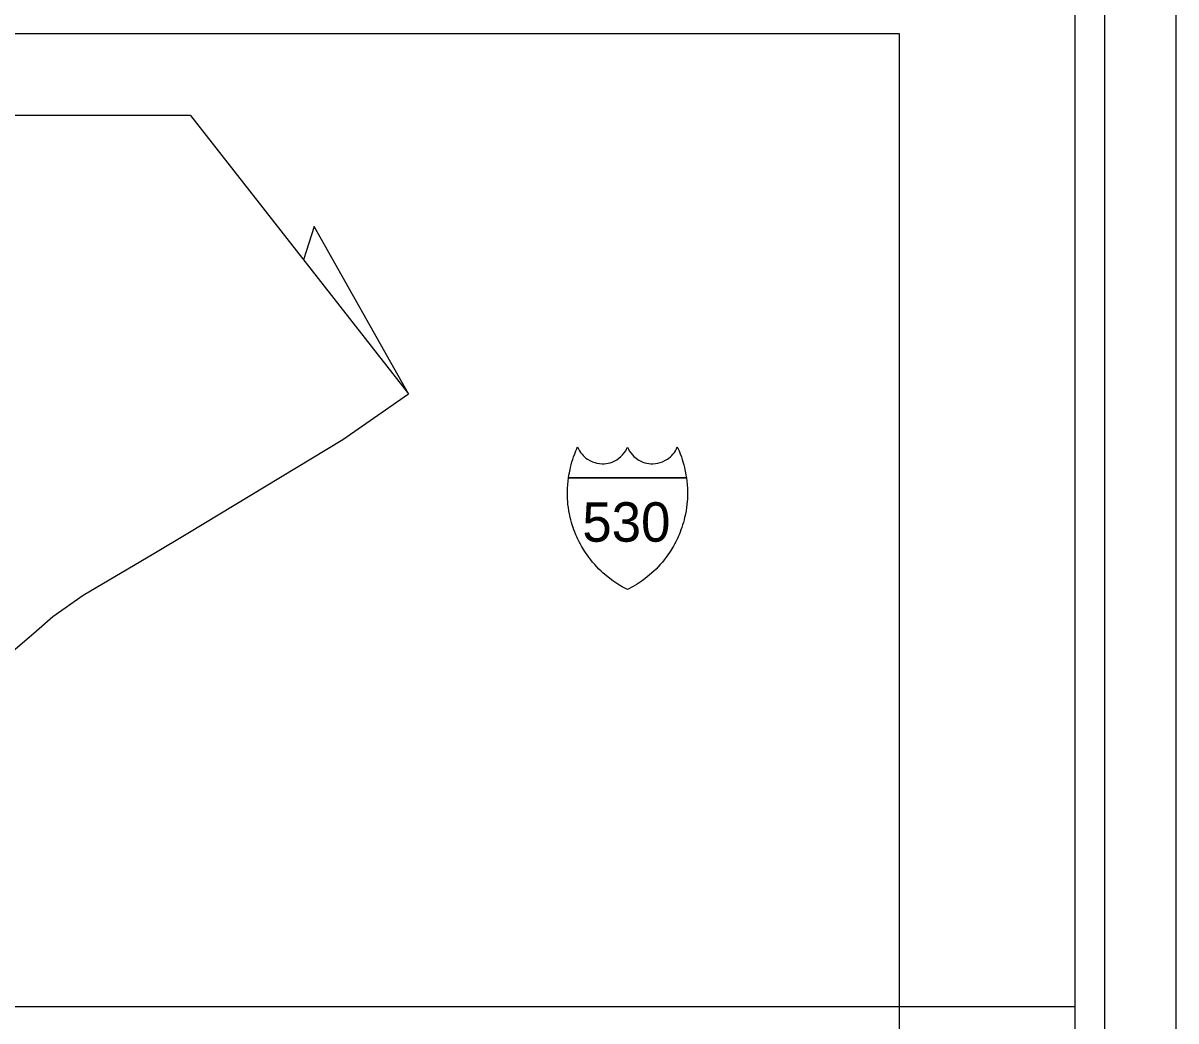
# Model space of a CAD drawing. Extents: x 10700 to 22009, y 10612 to 15552.
# Drawn here: x 16875 to 17646, y 14496 to 15164 of the extents above; entities that cross this region are included whole.
import ezdxf

# ---------------------------------------------------------------- set-up
doc = ezdxf.new("R2010")
doc.units = 0
for name, color, linetype in [('23', 7, 'Continuous'), ('Default', 7, 'Continuous'), ('R_Border', 7, 'Continuous'), ('R_Dimension', 7, 'Continuous'), ('R_No Plot', 7, 'Continuous')]:
    doc.layers.add(name, color=color, linetype=linetype)

msp = doc.modelspace()

# ---------------------------------------------------------------- linework, layer by layer
at = {"layer": '23'}
for points in [[(17239.63, 14859.64), (17239.92, 14861.53), (17240.22, 14863.19), (17240.66, 14865.34), (17240.98, 14866.74), (17241.4, 14868.41), (17241.95, 14870.36), (17242.46, 14871.99), (17243.02, 14873.68), (17243.77, 14875.75), (17244.55, 14877.69), (17245.19, 14879.19), (17245.73, 14880.38), (17246.31, 14879.1), (17246.98, 14877.88), (17247.71, 14876.76), (17248.67, 14875.52), (17249.43, 14874.68), (17250.37, 14873.77), (17251.32, 14872.98), (17252.35, 14872.23), (17253.98, 14871.25), (17255.66, 14870.47), (17257.18, 14869.93), (17258.68, 14869.54), (17260.29, 14869.28), (17262.16, 14869.15), (17263.39, 14869.18), (17264.81, 14869.31), (17266.06, 14869.52), (17267.41, 14869.86), (17268.77, 14870.31), (17270.59, 14871.11), (17271.85, 14871.81), (17273.31, 14872.81), (17274.71, 14873.99), (17275.74, 14875.03), (17276.9, 14876.44), (17277.87, 14877.89), (17278.43, 14878.9), (17279.06, 14880.23)], [(17279.06, 14880.23), (17279.68, 14878.9), (17280.24, 14877.89), (17281.21, 14876.44), (17282.38, 14875.03), (17283.4, 14873.99), (17284.8, 14872.81), (17286.26, 14871.81), (17287.52, 14871.11), (17289.35, 14870.31), (17290.7, 14869.86), (17292.05, 14869.52), (17293.31, 14869.31), (17294.72, 14869.18), (17295.95, 14869.15), (17297.82, 14869.28), (17299.43, 14869.54), (17300.93, 14869.93), (17302.45, 14870.47), (17304.13, 14871.25), (17305.76, 14872.23), (17306.79, 14872.98), (17307.74, 14873.77), (17308.68, 14874.68), (17309.44, 14875.52), (17310.4, 14876.76), (17311.13, 14877.88), (17311.8, 14879.1), (17312.39, 14880.38), (17312.92, 14879.19), (17313.57, 14877.69), (17314.34, 14875.75), (17315.09, 14873.68), (17315.65, 14871.99), (17316.16, 14870.36), (17316.71, 14868.41), (17317.13, 14866.74), (17317.45, 14865.34), (17317.9, 14863.19), (17318.19, 14861.53), (17318.48, 14859.64)], [(17279.06, 14784.95), (17275.6, 14786.8), (17272.56, 14788.62), (17269.22, 14790.88), (17266.1, 14793.25), (17262.68, 14796.16), (17261.41, 14797.34), (17259.96, 14798.76), (17258.62, 14800.14), (17257.15, 14801.75), (17255.71, 14803.43), (17254.51, 14804.91), (17253.2, 14806.61), (17252.02, 14808.25), (17250.99, 14809.76), (17250.09, 14811.15), (17249.34, 14812.35), (17248.36, 14814.04), (17247.59, 14815.42), (17246.74, 14817.03), (17245.92, 14818.69), (17245.21, 14820.24), (17244.56, 14821.72), (17243.88, 14823.39), (17243.29, 14824.94), (17242.72, 14826.56), (17242.17, 14828.25), (17241.65, 14829.97), (17241.2, 14831.62), (17240.81, 14833.19), (17240.49, 14834.59), (17240.28, 14835.62), (17239.9, 14837.63), (17239.54, 14839.95), (17239.29, 14841.88), (17239.12, 14843.91), (17239.01, 14845.56), (17238.93, 14847.65), (17238.91, 14849.6), (17238.95, 14851.77), (17239.01, 14853.2), (17239.09, 14854.51), (17239.15, 14855.33), (17239.36, 14857.46), (17239.63, 14859.64)], [(17318.48, 14859.64), (17239.63, 14859.64)], [(17239.63, 14859.64), (17318.48, 14859.64)], [(17318.48, 14859.64), (17318.75, 14857.46), (17318.96, 14855.33), (17319.02, 14854.51), (17319.1, 14853.2), (17319.16, 14851.77), (17319.2, 14849.6), (17319.18, 14847.65), (17319.1, 14845.56), (17319, 14843.91), (17318.82, 14841.88), (17318.57, 14839.95), (17318.21, 14837.63), (17317.84, 14835.62), (17317.62, 14834.59), (17317.3, 14833.19), (17316.91, 14831.62), (17316.46, 14829.97), (17315.94, 14828.25), (17315.39, 14826.56), (17314.82, 14824.94), (17314.23, 14823.39), (17313.55, 14821.72), (17312.9, 14820.24), (17312.19, 14818.69), (17311.37, 14817.03), (17310.52, 14815.42), (17309.76, 14814.04), (17308.77, 14812.35), (17308.03, 14811.15), (17307.12, 14809.76), (17306.1, 14808.25), (17304.91, 14806.61), (17303.61, 14804.91), (17302.4, 14803.43), (17300.96, 14801.75), (17299.49, 14800.14), (17298.15, 14798.76), (17296.7, 14797.34), (17295.43, 14796.16), (17292.02, 14793.25), (17288.89, 14790.88), (17285.55, 14788.62), (17282.51, 14786.8), (17279.06, 14784.95)]]:
    msp.add_lwpolyline(points, dxfattribs=at)
at = {"layer": 'Default'}
msp.add_lwpolyline([(16155.5, 14168.76), (16185.52, 14183.02), (16215.54, 14197.28), (16237.97, 14209.07), (16270.34, 14229.5), (16275.18, 14233.24), (16281.02, 14238.26), (16394.9, 14334.16), (16410.98, 14348.21), (16776.96, 14665.71), (16798.8, 14684.66), (16813.62, 14697.51), (16824.46, 14706.35), (16863.46, 14739.87), (16883.94, 14757.47), (16894.9, 14766.9), (16915.02, 14781.31), (16962.44, 14809.09), (16985.03, 14822.73), (17088.74, 14885.33), (17132.75, 14915.87)], dxfattribs=at)
at = {"layer": 'R_Border'}
msp.add_line((17598.27, 13458.53), (17598.27, 15513.13), dxfattribs=at)
at = {"layer": 'R_Dimension'}
msp.add_line((16986.85, 15102.14), (16565.62, 15102.14), dxfattribs=at)
msp.add_lwpolyline([(16986.85, 15102.14), (17132.75, 14915.87), (17069.65, 15027.91), (17062.51, 15005.55)], dxfattribs=at)
at = {"layer": 'R_No Plot'}
for points in [[(14312.4, 15552.08), (17645.8, 15552.08), (17645.8, 13418.7), (14312.4, 13418.7)], [(14456.47, 15493.13), (16951.87, 15493.13), (16951.87, 15394.33), (17127.27, 15394.33), (17368.27, 15394.33), (17368.27, 15171.01), (17578.27, 15171.01), (17578.27, 13478.53), (14456.47, 13478.53)], [(17578.27, 14505.83), (14456.47, 14505.83), (14456.47, 15493.13), (16951.87, 15493.13), (16951.87, 15394.33), (17127.27, 15394.33), (17368.27, 15394.33), (17368.27, 15171.01), (17578.27, 15171.01)], [(17460.65, 15156.83), (17460.65, 14032.05), (15915.54, 14032.05), (15915.54, 15156.83)]]:
    msp.add_lwpolyline(points, close=True, dxfattribs=at)

# ---------------------------------------------------------------- texts
at = {"layer": '23'}
msp.add_text('530', height=26.4, dxfattribs=at).set_placement((17248.88, 14817.01))

doc.saveas('drawing.dxf')
